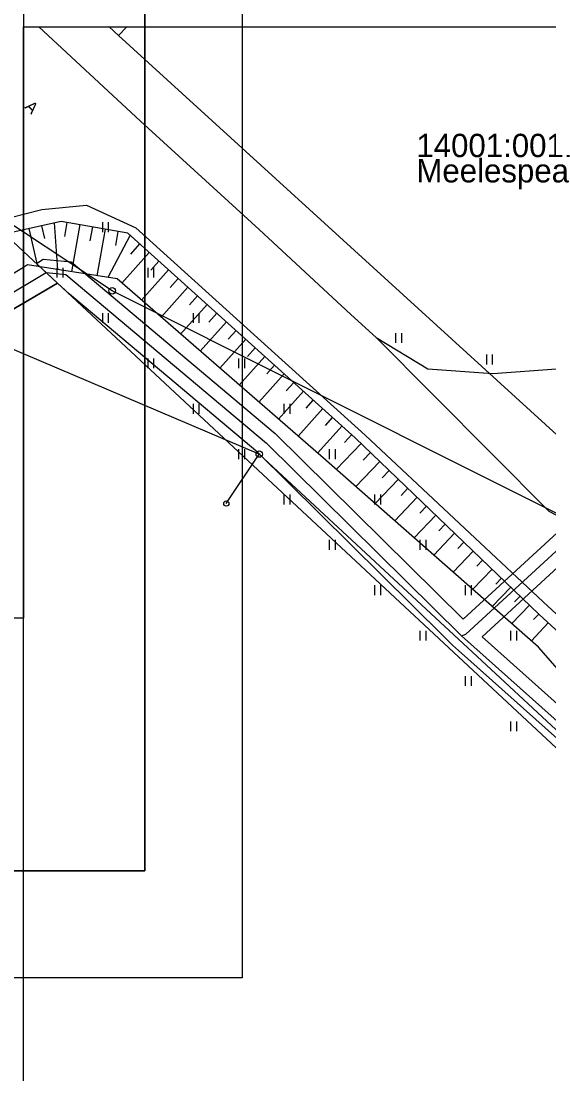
# Model space of a CAD drawing. Extents: x 567864 to 568657, y 6579839 to 6580994.
# Drawn here: x 568384.5 to 568425.2, y 6580410.7 to 6580491.9 of the extents above; entities that cross this region are included whole.
import ezdxf

# ---------------------------------------------------------------- set-up
doc = ezdxf.new("R2010")
doc.units = 0
for name, color, linetype in [('HALJASTUS', 7, 'Continuous'), ('KASUTUSALA', 7, 'Continuous'), ('KPOHULIIN', 7, 'Continuous'), ('MPOHULIIN', 7, 'Continuous'), ('PIIR', 7, 'Continuous'), ('POST', 7, 'Continuous'), ('PR_SIDE', 7, 'Continuous'), ('RELJEEF', 7, 'Continuous'), ('TEE', 7, 'Continuous'), ('VORMISTUS_2', 7, 'Continuous'), ('VORMISTUS_3', 7, 'Continuous')]:
    doc.layers.add(name, color=color, linetype=linetype)

msp = doc.modelspace()

# ---------------------------------------------------------------- linework, layer by layer
at = {"layer": 'HALJASTUS'}
for p, q in [((568390.772, 6580476.381), (568390.772, 6580475.619)), ((568391.228, 6580476.381), (568391.228, 6580475.619)), ((568387.272, 6580472.881), (568387.272, 6580472.119)), ((568387.728, 6580472.881), (568387.728, 6580472.119)), ((568394.272, 6580472.881), (568394.272, 6580472.119)), ((568394.728, 6580472.881), (568394.728, 6580472.119)), ((568390.772, 6580469.381), (568390.772, 6580468.619)), ((568391.228, 6580469.381), (568391.228, 6580468.619)), ((568397.772, 6580469.381), (568397.772, 6580468.619)), ((568398.228, 6580469.381), (568398.228, 6580468.619)), ((568413.389, 6580467.838), (568413.389, 6580467.077)), ((568413.844, 6580467.838), (568413.844, 6580467.077)), ((568420.399, 6580466.187), (568420.399, 6580465.426)), ((568420.854, 6580466.187), (568420.854, 6580465.426)), ((568394.272, 6580465.881), (568394.272, 6580465.119)), ((568394.728, 6580465.881), (568394.728, 6580465.119)), ((568401.272, 6580465.881), (568401.272, 6580465.119)), ((568401.728, 6580465.881), (568401.728, 6580465.119)), ((568397.772, 6580462.381), (568397.772, 6580461.619)), ((568398.228, 6580462.381), (568398.228, 6580461.619)), ((568404.772, 6580462.381), (568404.772, 6580461.619)), ((568405.228, 6580462.381), (568405.228, 6580461.619)), ((568401.272, 6580458.881), (568401.272, 6580458.119)), ((568401.728, 6580458.881), (568401.728, 6580458.119)), ((568408.272, 6580458.881), (568408.272, 6580458.119)), ((568408.728, 6580458.881), (568408.728, 6580458.119)), ((568404.772, 6580455.381), (568404.772, 6580454.619)), ((568405.228, 6580455.381), (568405.228, 6580454.619)), ((568411.772, 6580455.381), (568411.772, 6580454.619)), ((568412.228, 6580455.381), (568412.228, 6580454.619)), ((568408.272, 6580451.881), (568408.272, 6580451.119)), ((568408.728, 6580451.881), (568408.728, 6580451.119)), ((568415.272, 6580451.881), (568415.272, 6580451.119)), ((568415.728, 6580451.881), (568415.728, 6580451.119)), ((568411.772, 6580448.381), (568411.772, 6580447.619)), ((568412.228, 6580448.381), (568412.228, 6580447.619)), ((568418.772, 6580448.381), (568418.772, 6580447.619)), ((568419.228, 6580448.381), (568419.228, 6580447.619)), ((568415.272, 6580444.881), (568415.272, 6580444.119)), ((568415.728, 6580444.881), (568415.728, 6580444.119)), ((568422.272, 6580444.881), (568422.272, 6580444.119)), ((568422.728, 6580444.881), (568422.728, 6580444.119)), ((568418.772, 6580441.381), (568418.772, 6580440.619)), ((568419.228, 6580441.381), (568419.228, 6580440.619)), ((568422.272, 6580437.881), (568422.272, 6580437.119)), ((568422.728, 6580437.881), (568422.728, 6580437.119))]:
    msp.add_line(p, q, dxfattribs=at)
at = {"layer": 'KASUTUSALA'}
msp.add_lwpolyline([(568493.207, 6580374.737), (568460.062, 6580405.872), (568437.58, 6580426.106), (568418.255, 6580443.353), (568417.794, 6580443.764), (568417.1, 6580444.45), (568402.76, 6580458.616), (568388.236, 6580470.827), (568387.31, 6580471.69), (568385.679, 6580473.21), (568386.212, 6580473.528), (568388.359, 6580473.336), (568404.109, 6580460.095), (568418.602, 6580445.777), (568429.97, 6580456.218), (568431.455, 6580454.865), (568420.072, 6580444.412), (568438.915, 6580427.595), (568461.416, 6580407.344), (568494.568, 6580376.202)], dxfattribs=at)
at = {"layer": 'KPOHULIIN'}
for points in [[(568384.68, 6580466.246), (568359.848, 6580476.807), (568357.32, 6580478.049), (568301.591, 6580445.85)], [(568508.43, 6580360.63), (568460.118, 6580405.359), (568402.883, 6580458.504), (568384.68, 6580466.246)]]:
    msp.add_lwpolyline(points, dxfattribs=at)
at = {"layer": 'MPOHULIIN'}
for points in [[(568384.68, 6580475.615), (568373.443, 6580483.03), (568365.788, 6580481.372)], [(568435.851, 6580448.911), (568391.527, 6580471.097), (568384.68, 6580475.615)]]:
    msp.add_lwpolyline(points, dxfattribs=at)
at = {"layer": 'PIIR'}
for points in [[(568384.68, 6580474.141), (568373.5, 6580484.56), (568289.57, 6580562.8), (568260.93, 6580590.136)], [(568391.299, 6580491.456), (568392.03, 6580490.79), (568429.88, 6580456.3), (568437.22, 6580449.61), (568476.19, 6580414.1), (568508.43, 6580384.732)], [(568392.661, 6580491.456), (568392.03, 6580490.79), (568391.3, 6580491.456)], [(568447.578, 6580491.456), (568452.98, 6580486.06), (568453.13, 6580479.23), (568429.88, 6580456.3), (568392.03, 6580490.79), (568392.661, 6580491.456)], [(568310.296, 6580445.85), (568373.5, 6580484.56), (568384.68, 6580474.141)], [(568508.43, 6580358.861), (568387.31, 6580471.69), (568384.68, 6580474.141)], [(568384.68, 6580474.141), (568387.31, 6580471.69), (568384.68, 6580470.154)], [(568384.68, 6580470.154), (568387.31, 6580471.69), (568508.43, 6580358.861)], [(568384.68, 6580470.154), (568343.069, 6580445.85)], [(568343.069, 6580445.85), (568384.68, 6580470.154)]]:
    msp.add_lwpolyline(points, dxfattribs=at)
at = {"layer": 'POST'}
msp.add_lwpolyline([(568400.338, 6580454.689), (568402.883, 6580458.504)], dxfattribs=at)
for centre, radius in [((568391.527, 6580471.097), 0.25), ((568402.883, 6580458.504), 0.25), ((568402.883, 6580458.504), 0.0234), ((568400.338, 6580454.689), 0.2)]:
    msp.add_circle(centre, radius, dxfattribs=at)
at = {"layer": 'PR_SIDE'}
for points in [[(568365.055, 6580475.025), (568365.72, 6580474.689), (568366.357, 6580474.88), (568372.77, 6580480.661), (568373.5, 6580480.629), (568382.621, 6580470.383), (568382.924, 6580470.401), (568386.446, 6580472.503), (568387.957, 6580472.369), (568403.435, 6580459.356), (568418.48, 6580444.494), (568418.81, 6580444.61), (568431.813, 6580456.552), (568437.233, 6580461.195), (568454.71, 6580479.772), (568455.401, 6580480.844), (568455.401, 6580484.611)], [(568418.48, 6580444.494), (568438.248, 6580426.851), (568460.739, 6580406.609), (568493.888, 6580375.47), (568520.606, 6580350.928), (568532.176, 6580339.842), (568577.376, 6580298.14), (568583.801, 6580292.735), (568596.758, 6580277.054), (568604.332, 6580268.007), (568619.547, 6580250.982), (568628.574, 6580238.417), (568627.426, 6580222.172)]]:
    msp.add_lwpolyline(points, dxfattribs=at)
at = {"layer": 'RELJEEF'}
for p, q in [((568385.11, 6580475.896), (568385.769, 6580472.98)), ((568386.085, 6580476.116), (568386.309, 6580475.125)), ((568387.06, 6580476.337), (568387.312, 6580472.738)), ((568388.04, 6580476.376), (568387.846, 6580475.281)), ((568389.024, 6580476.202), (568388.38, 6580472.57)), ((568390.009, 6580476.027), (568389.817, 6580474.943)), ((568390.994, 6580475.852), (568390.357, 6580472.259)), ((568391.978, 6580475.678), (568391.788, 6580474.606)), ((568392.906, 6580475.387), (568391.199, 6580472.127)), ((568394.394, 6580474.05), (568392.277, 6580471.696)), ((568393.65, 6580474.719), (568392.947, 6580473.936)), ((568395.137, 6580473.382), (568394.506, 6580472.679)), ((568395.881, 6580472.713), (568393.787, 6580470.384)), ((568396.625, 6580472.045), (568396, 6580471.35)), ((568397.369, 6580471.376), (568395.298, 6580469.072)), ((568398.856, 6580470.039), (568396.808, 6580467.761)), ((568398.112, 6580470.708), (568397.494, 6580470.02)), ((568399.6, 6580469.37), (568398.989, 6580468.691)), ((568400.343, 6580468.702), (568398.318, 6580466.449)), ((568401.087, 6580468.033), (568400.483, 6580467.361)), ((568401.831, 6580467.365), (568399.828, 6580465.138)), ((568403.318, 6580466.028), (568401.339, 6580463.826)), ((568402.574, 6580466.696), (568401.977, 6580466.032)), ((568404.062, 6580465.359), (568403.471, 6580464.703)), ((568404.805, 6580464.691), (568402.849, 6580462.514)), ((568405.549, 6580464.022), (568404.965, 6580463.373)), ((568406.293, 6580463.354), (568404.359, 6580461.203)), ((568407.036, 6580462.685), (568406.46, 6580462.044)), ((568407.78, 6580462.017), (568405.869, 6580459.891)), ((568408.524, 6580461.348), (568407.954, 6580460.714)), ((568409.267, 6580460.68), (568407.38, 6580458.579)), ((568410.011, 6580460.011), (568409.447, 6580459.384)), ((568410.74, 6580459.327), (568408.814, 6580457.322)), ((568411.462, 6580458.634), (568410.893, 6580458.042)), ((568412.183, 6580457.941), (568410.319, 6580456.001)), ((568412.904, 6580457.249), (568412.354, 6580456.676)), ((568413.625, 6580456.556), (568411.823, 6580454.68)), ((568414.346, 6580455.863), (568413.815, 6580455.31)), ((568415.067, 6580455.17), (568413.327, 6580453.359)), ((568416.51, 6580453.785), (568414.832, 6580452.038)), ((568415.788, 6580454.478), (568415.276, 6580453.944)), ((568417.231, 6580453.092), (568416.737, 6580452.578)), ((568417.952, 6580452.399), (568416.336, 6580450.717)), ((568418.673, 6580451.706), (568418.198, 6580451.212)), ((568419.394, 6580451.014), (568417.841, 6580449.396)), ((568420.115, 6580450.321), (568419.659, 6580449.845)), ((568420.837, 6580449.628), (568419.345, 6580448.075)), ((568421.558, 6580448.935), (568421.12, 6580448.479)), ((568422.279, 6580448.243), (568420.849, 6580446.755)), ((568423, 6580447.55), (568422.58, 6580447.113)), ((568423.721, 6580446.857), (568422.354, 6580445.434)), ((568424.442, 6580446.164), (568424.041, 6580445.747)), ((568425.178, 6580445.487), (568423.891, 6580444.084))]:
    msp.add_line(p, q, dxfattribs=at)
for points in [[(568508.43, 6580369.908), (568508.363, 6580369.97), (568491.192, 6580385.824), (568473.185, 6580402.248), (568453.996, 6580419.435), (568439.254, 6580432.576), (568424.484, 6580446.124), (568410.28, 6580459.769), (568392.732, 6580475.544), (568387.587, 6580476.456), (568384.68, 6580475.798)], [(568384.68, 6580475.798), (568382.323, 6580475.265), (568376.904, 6580471.885)], [(568384.68, 6580472.903), (568380.121, 6580470.149)], [(568508.43, 6580367.153), (568506.784, 6580368.671), (568490.34, 6580384.468), (568471.539, 6580401.225), (568453.41, 6580417.781), (568436.551, 6580429.766), (568424.43, 6580443.611), (568407.632, 6580458.36), (568391.91, 6580472.015), (568385.007, 6580473.1), (568384.68, 6580472.903)]]:
    msp.add_lwpolyline(points, dxfattribs=at)
at = {"layer": 'TEE'}
for points in [[(568508.43, 6580378.848), (568495.331, 6580390.846), (568482.748, 6580402.025), (568475.413, 6580408.617), (568468.573, 6580415.051), (568463.218, 6580419.847), (568458.453, 6580424.255), (568444.275, 6580436.505), (568431.318, 6580448.81), (568430.178, 6580450.348), (568426.969, 6580453.169), (568425.251, 6580454.077), (568411.891, 6580467.485), (568409.943, 6580469.266), (568402.862, 6580475.838), (568393.707, 6580484.18), (568385.876, 6580491.456)], [(568411.891, 6580467.485), (568415.882, 6580465.074), (568420.903, 6580464.715), (568425.819, 6580465.089), (568431.98, 6580465.58), (568436.401, 6580466.715), (568442.096, 6580470.806), (568443.907, 6580474.414), (568443.977, 6580478.683), (568442.212, 6580482.999), (568438.678, 6580487.427), (568434.981, 6580491.456)], [(568384.68, 6580477.004), (568386.096, 6580477.365), (568389.562, 6580477.715), (568393.349, 6580475.969), (568411.045, 6580459.971), (568424.789, 6580447.111), (568440.147, 6580432.905), (568454.13, 6580420.179), (568473.798, 6580402.405), (568491.299, 6580386.419), (568508.43, 6580370.472)], [(568329.478, 6580445.85), (568340.167, 6580451.854), (568359.869, 6580462.756), (568375.146, 6580471.713), (568379.668, 6580474.818), (568383.09, 6580476.599), (568384.68, 6580477.004)]]:
    msp.add_lwpolyline(points, dxfattribs=at)
at = {"layer": 'VORMISTUS_2'}
for points in [[(568244.055, 6580640.85), (568401.555, 6580640.85), (568401.555, 6580418.1), (568244.055, 6580418.1)], [(568251.555, 6580426.35), (568394.055, 6580426.35), (568394.055, 6580632.6), (568251.555, 6580632.6)], [(568251.555, 6580632.6), (568394.055, 6580632.6), (568394.055, 6580426.35), (568251.555, 6580426.35)], [(568384.68, 6580445.85), (568260.93, 6580445.85), (568260.93, 6580603.35), (568384.68, 6580603.35)]]:
    msp.add_lwpolyline(points, close=True, dxfattribs=at)
at = {"layer": 'VORMISTUS_3'}
msp.add_lwpolyline([(568508.43, 6580333.956), (568384.68, 6580333.956), (568384.68, 6580491.456), (568508.43, 6580491.456)], close=True, dxfattribs=at)

# ---------------------------------------------------------------- texts
at = {"layer": 'PIIR'}
for s, p in [('14001:001:0375', (568415.001, 6580481.411)), ('Meelespea', (568415.001, 6580479.461))]:
    msp.add_text(s, height=1.8, dxfattribs=at).set_placement(p)
at = {"layer": 'TEE'}
msp.add_text('A', height=0.9, rotation=315.25757, dxfattribs=at).set_placement((568384.729, 6580485.232))

doc.saveas('drawing.dxf')
